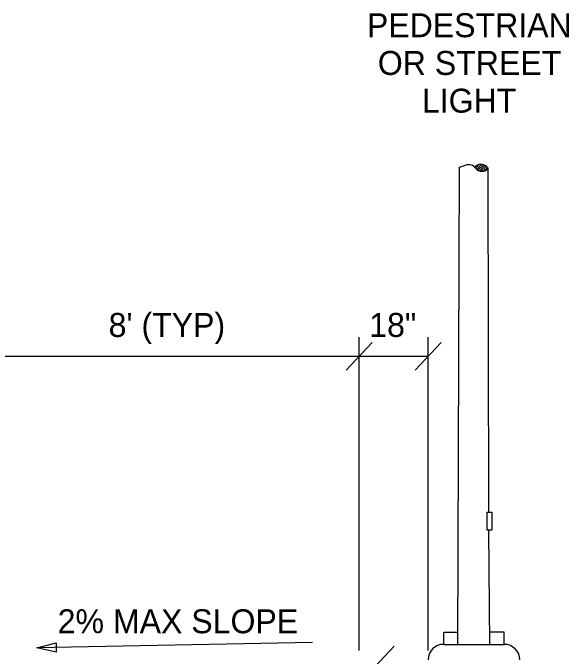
# Model space of a CAD drawing. Extents: x 27101070.6 to 27101150.6, y 1158854.7 to 1158902.9.
# Drawn here: x 27101126.13 to 27101138.25, y 1158888.86 to 1158902.88 of the extents above; entities that cross this region are included whole.
import ezdxf

# ---------------------------------------------------------------- set-up
doc = ezdxf.new("R2010")
doc.units = 0
for name, color, linetype in [('G-ANNO-TEXT', 7, 'Continuous'), ('G-DETL-OTLN', 7, 'Continuous'), ('G-DETL-PATT', 7, 'Continuous')]:
    doc.layers.add(name, color=color, linetype=linetype)

msp = doc.modelspace()

# ---------------------------------------------------------------- linework, layer by layer
at = {"layer": 'G-ANNO-TEXT'}
for p, q in [((27101133.394, 1158895.093), (27101133.958, 1158895.695)), ((27101133.676, 1158888.983), (27101133.676, 1158895.815)), ((27101134.894, 1158895.093), (27101135.458, 1158895.695)), ((27101135.176, 1158888.983), (27101135.176, 1158895.815)), ((27101081.176, 1158895.396), (27101135.176, 1158895.396)), ((27101132.656, 1158889.161), (27101126.658, 1158889.041)), ((27101133.871, 1158888.478), (27101134.434, 1158889.079))]:
    msp.add_line(p, q, dxfattribs=at)
msp.add_lwpolyline([(27101127.077, 1158888.946), (27101126.658, 1158889.041), (27101127.073, 1158889.154)], close=True, dxfattribs=at)
at = {"layer": 'G-DETL-OTLN'}
for p, q in [((27101135.826, 1158889.119), (27101135.861, 1158899.515)), ((27101136.497, 1158892.002), (27101136.486, 1158899.493)), ((27101136.46, 1158892.002), (27101136.565, 1158892.002)), ((27101136.46, 1158891.607), (27101136.46, 1158892.002)), ((27101136.565, 1158892.002), (27101136.565, 1158891.607)), ((27101136.565, 1158891.607), (27101136.46, 1158891.607)), ((27101136.521, 1158889.119), (27101136.5, 1158891.607)), ((27101135.515, 1158889.386), (27101135.829, 1158889.384)), ((27101135.515, 1158889.119), (27101135.515, 1158889.386)), ((27101136.833, 1158889.386), (27101136.518, 1158889.384)), ((27101136.833, 1158889.119), (27101136.833, 1158889.386)), ((27101135.515, 1158889.119), (27101136.833, 1158889.119))]:
    msp.add_line(p, q, dxfattribs=at)
for points in [[(27101135.861, 1158899.515), (27101135.991, 1158899.559)], [(27101136.486, 1158899.493), (27101136.446, 1158899.531)]]:
    msp.add_lwpolyline(points, dxfattribs=at)
for centre, radius, start, end in [((27101136.054, 1158899.371), 0.198, 38.0577, 108.5231), ((27101136.322, 1158899.398), 0.181, 46.9962, 138.5136), ((27101136.348, 1158899.601), 0.175, 218.0577, 321.992), ((27101135.515, 1158888.778), 0.341, 90, 180), ((27101136.833, 1158888.778), 0.341, 360, 90)]:
    msp.add_arc(centre, radius, start, end, dxfattribs=at)
at = {"layer": 'G-DETL-PATT'}
for p, q in [((27101136.209, 1158899.495), (27101136.289, 1158899.575)), ((27101136.233, 1158899.471), (27101136.339, 1158899.577)), ((27101136.261, 1158899.451), (27101136.378, 1158899.568)), ((27101136.295, 1158899.436), (27101136.413, 1158899.554)), ((27101136.333, 1158899.427), (27101136.441, 1158899.534)), ((27101136.385, 1158899.43), (27101136.467, 1158899.512))]:
    msp.add_line(p, q, dxfattribs=at)

# ---------------------------------------------------------------- texts
at = {"layer": 'G-ANNO-TEXT'}
for s, p in [('PEDESTRIAN', (27101133.842, 1158902.348)), ('OR STREET', (27101134.08, 1158901.526)), ('LIGHT', (27101135.04, 1158900.704)), ("8' (TYP)", (27101128.218, 1158895.817)), ('18"', (27101133.893, 1158895.817)), ('2% MAX SLOPE ', (27101127.109, 1158889.361))]:
    msp.add_text(s, height=0.522, dxfattribs=at).set_placement(p)

doc.saveas('drawing.dxf')
